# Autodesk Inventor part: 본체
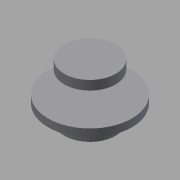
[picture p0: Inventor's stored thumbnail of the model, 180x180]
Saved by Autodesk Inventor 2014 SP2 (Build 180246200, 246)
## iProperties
Created: 2024-04
Part Number: 본체
Material: Generic
Document SubType Name: Modeling
Designer: Administrator
Density: 1 g/cm^3
Appearance: Default
Author: Administrator
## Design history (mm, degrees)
sketch "스케치1"
  geometry: L1 (-76.3, 0)-(76.3, 0) reference; L2 (0, -76.3)-(0, 76.3) reference; C1 r 54.5 at (0, 0); 1 further point
  constraints: 1 centre point, 1 coincident
  dimensions: "d0" = 109 diameter of C1
extrude "돌출1" new body sketch "스케치1" distance "d1" = 10; taper "d2" = 0 deg
sketch "스케치2"
  geometry: C1 r 54.5 at (0, 0) reference; C2 r 38.5 at (0, 0)
  constraints: 1 centre point, 1 coincident
  dimensions: "d3" = 77 diameter of C2
extrude "돌출2" join sketch "스케치2" distance "d4" = 5; taper "d5" = 0 deg
sketch "스케치3"
  geometry: C1 r 38.5 at (0, 0) reference; C2 r 33.5 at (0, 0)
  constraints: 1 centre point, 1 coincident
  dimensions: "d6" = 67 diameter of C2
extrude "돌출3" join sketch "스케치3" distance "d7" = 15; taper "d8" = 0 deg
node "작업 평면1"
sketch "스케치6"
  geometry: C1 r 33.5 at (0, 0); 1 further point
  constraints: 1 centre point, 1 coincident
  dimensions: "d10" = 67 diameter of C1
extrude "돌출4" join sketch "스케치6" distance "d11" = 12; taper "d12" = 0 deg
node "솔리드1"
